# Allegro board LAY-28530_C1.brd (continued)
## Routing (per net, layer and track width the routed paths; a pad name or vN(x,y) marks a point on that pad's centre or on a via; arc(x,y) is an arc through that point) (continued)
DDR4_VTT: length 59.1
  TOP w0.254: C158.1 87.05,9.14 87.05,12.11 88.32,13.38 91.5,13.38 92,13.89 92,14.78 92.28,15.05 U38.19
  TOP w0.305: 172.27,27.86 172.65,28.24 C121.1
  TOP w0.508: R177.1 171.13,17.57 ; R182.1 171.13,13.13 ; R176.1 171.25,18.59 ; R175.1 171.25,19.61 ; R168.1 171.25,25.7 ; C119.1 170.24,27.86 ; R169.1 171.25,24.69 ; R171.1 171.13,22.65 ; R173.1 171.25,21.64 ; R174.1 171.13,20.62 ; R181.1 171.25,14.15 ; R170.1 171.13,23.67 ; C120.1 171.51,27.86
  BOTTOM w0.254: 110.94,12.62 C589.1 ; C589.1 112.19,12.62 ; C589.1 111.56,12 ; 113.48,12.62 C587.1 114.1,12 ; 110.92,12.11 C591.1 110.04,11.36 ; C585.1 117.14,12.62 ; C585.1 115.89,12.62 ; C585.1 116.52,12 ; 112.21,12.62 C588.1 ; C588.1 113.46,12.62 ; C588.1 112.83,12 ; 115.87,12.62 C586.1 115.25,12 ; 117.91,12 C584.1 ; C584.1 117.29,12.62 ; C584.1 118.54,12.62
  BOTTOM w0.381: 171,27.73 171.02,27.76 C486.1 ; C487.1 169.75,27.76 169.73,27.73 ; C593.1 v1(152.08,11.35)
  BOTTOM w0.508: R171.1 171.25,22.65 ; R176.1 171.38,18.59 ; R170.1 171.25,23.67 ; R169.1 171.25,24.69 ; C599.1 v1(156.9,10.84) ; C595.1 v1(138.99,11.35) ; R174.1 171.25,20.62 ; R168.1 171.25,25.7 ; R173.1 171.25,21.64 ; R181.1 171.38,14.15 ; C594.1 v1(143.57,11.22) ; R177.1 171.13,17.57 ; R175.1 171.38,19.61
  BOTTOM w0.533: C605.1 170.86,10.08 ; C605.1 170.24,9.46 ; C605.1 170.24,10.7 ; 170.36,12.51 R182.1 170.99,13.13 ; C600.1 170.86,11.48 ; C600.1 170.24,12.1 ; C600.1 170.24,10.86 ; 172.17,27.87 C485.1 172.79,28.5 ; 170.36,15.78 R180.1 170.99,15.16 ; 170.36,27.34 R166.1 170.99,26.72 ; 170.86,8.68 C606.1 170.24,9.31 ; 170.99,16.56 R178.1 170.36,15.94
  vias: v1(112.2,11.1) v1(113.21,11.1) v1(114.36,11.1) v1(115.88,11.1) v1(117.4,11.1) v1(118.55,11.1) v1(171.89,27.1) v1(171.89,25.96) v1(171.89,24.81) v1(171.89,23.67) v1(171.89,22.4) v1(171.89,21.38) v1(171.89,20.11) v1(171.89,18.97) v1(171.89,17.57) v1(171.89,16.18) v1(171.89,14.65) v1(171.89,13.13) v1(171.89,11.86) v1(171.89,10.84) v1(171.89,9.83)
EC1_AVDD10: length 22.1
  TOP w0.203: v1(107.37,135.68) 107.27,135.58 U5.47 ; U5.9 v1(102.43,137.59) ; U5.4 v1(104.44,137.59)
  TOP w0.508: R66.2 v1(110.55,127.05)
  L3_INT1 w0.508: v1(110.55,127.05) 110.55,128.19 107.37,131.37 v1(107.37,135.68) 106.48,136.57 105.47,136.57 104.45,137.59 v1(104.44,137.59) v1(102.43,137.59)
  BOTTOM w0.508: C205.2 102.42,137.57 v1(102.43,137.59) ; v1(104.44,137.59) 103.94,137.1 C204.2 ; C215.2 v1(107.37,135.68)
EC1_CLK_125M: length 80.3
  TOP w0.127: U21.W4 v2(135,70.81)
  TOP w0.203: R50.2 C42.1 110.29,130.1 110.67,130.48 v1(115.12,130.48)
  L3_INT1 w0.127: v1(115.12,130.48) 114.36,129.72 114.36,120.83 121.85,113.33 121.85,98.6 128.33,92.12 132.64,92.12 135.18,89.58 135.18,83.49 v1(134.68,82.98) 134.6,82.9 134.6,71.21 v2(135,70.81)
  BOTTOM w0.152: v1(134.68,82.98) 134.3,82.6 R404.1
EC1_DVDD10: length 17.4
  TOP w0.203: U5.22 99.37,132.38 v1(99.24,132.26)
  TOP w0.508: R74.2 v1(110.55,125.4)
  L3_INT1 w0.508: v1(110.55,125.4) 109.78,125.4 104.07,131.11 100.39,131.11 v1(99.24,132.26)
  BOTTOM w0.381: C222.2 99.62,132.64 v1(99.24,132.26)
EC1_DVDD_3V3: length 42.1
  TOP w0.203: U5.30 103.23,129.51 102.93,129.21 v1(102.93,128.32)
  TOP w0.381: R70.2 v1(114.99,126.16) ; R34.1 v1(95.69,136.07) ; R57.2 v1(114.99,129.46)
  L3_INT1 w0.381: v1(95.69,136.07) 98.23,136.07 98.99,135.3 98.99,134.16 98.61,133.78 98.61,131.49 101.78,128.32 v1(102.93,128.32)
  L4_INT2 w0.508: v1(114.99,126.16) 114.1,127.05 114.1,128.19 114.99,129.08 v1(114.99,129.46) 113.98,130.48 109.91,130.48 107.12,127.68 103.56,127.68 v1(102.93,128.32)
  BOTTOM w0.508: C236.2 102.93,129.84 v1(102.93,128.32) 102.29,127.68 C247.1 101.66,127.05 102.16,126.54 R221.2
EC1_DVDDRG: length 9.3
  TOP w0.203: v1(102.04,128.95) 102.84,129.75 U5.29
  BOTTOM w0.381: R217.2 97.21,128.57 97.59,128.95 98.23,128.95 99.5,130.22 C229.1
  BOTTOM w0.508: C229.1 100.77,130.22 101.02,129.97 C237.2 101.66,129.33 v1(102.04,128.95)
EC1_LED0/PHYAD0: length 181.9
  TOP w0.203: U5.35 105.24,130.2 106.99,128.45 110.55,128.45 112.45,126.54 R70.1 112.45,125.02 v1(112.58,124.89)
  TOP w0.305: C24.1 v1(92.89,138.81) 93.3,139.21 J4.17
  L3_INT1 w0.254: v1(92.89,138.81) 93.73,137.97 99.37,137.97 101.66,135.68 105.59,135.68 106.23,135.05 106.23,130.1 110.17,126.16 111.31,126.16 v1(112.58,124.89)
  L4_INT2 w0.203: v1(112.58,124.89) 112.58,107.11 109.53,104.06 109.53,65.96 112.32,63.17 112.32,47.55 109.91,45.13 109.91,39.67 105.72,35.48 105.72,15.92 109.66,11.99 109.66,10.21 114.23,5.64 v1(114.23,2.97)
  BOTTOM w0.203: C608.1 113.85,3.35 v1(114.23,2.97)
  BOTTOM w0.254: v1(114.23,2.97) 117.05,2.97 D12.4
EC1_LED1/CFG_LDO0: length 146.1
  TOP w0.203: R63.2 111.94,127.81 v1(111.44,128.32) 110.8,128.95 107.12,128.95 105.63,130.44 U5.36
  TOP w0.254: v1(112.71,136.32) 112.96,136.57 R31.1
  L3_INT1 w0.254: v1(111.44,128.32) 112.07,128.95 112.07,135.68 v1(112.71,136.32)
  L4_INT2 w0.203: v1(109.02,10.34) 109.02,11.99 104.7,16.3 104.7,35.23 109.53,40.05 109.53,45.39 111.94,47.8 111.94,62.79 109.15,65.58 109.15,104.4 112.07,107.32 112.07,124.64 111.44,125.27 v1(111.44,128.32)
  BOTTOM w0.203: R396.1 110.17,9.19 v1(109.02,10.34)
EC1_LED2/CFG_LDO1: length 7.6
  TOP w0.203: R57.1 v1(111.31,129.46) 107.37,129.46 106.37,130.46 106.37,131.58 U5.37
EC1_MDIN0: length 10.4
  TOP w0.104: v1(104.65,138.35) 104.88,138.12 104.88,137.44 104.83,137.39 U5.3
  L3_INT1 w0.104: J4.10 104.54,144.36 104.86,144.04 104.86,143.39 105.31,142.93 106.08,142.93 106.62,142.39 106.62,140.66 104.82,138.87 104.82,138.52 v1(104.65,138.35)
EC1_MDIN1: length 15.3
  TOP w0.104: v1(103.56,140.13) 103.56,140 103.68,139.88 103.68,137.44 103.64,137.39 U5.6
  L3_INT1 w0.104: v1(103.56,140.13) 103.73,139.96 103.73,139.57 104.05,139.25 104.73,139.25 105.21,139.73 105.21,140.51 102.93,142.8 102.93,144.81 104.21,146.1 104.21,146.75 104.36,146.9 J4.5
EC1_MDIN2: length 12.3
  TOP w0.104: U5.8 102.84,137.39 102.88,137.44 102.88,137.96 v1(102.5,138.35)
  L3_INT1 w0.104: J4.2 99.46,146.9 99.78,146.57 99.78,146.07 101.41,144.44 101.41,141.75 102.68,140.49 102.68,138.93 102.5,138.75 v1(102.5,138.35)
EC1_MDIN3: length 10.6
  TOP w0.104: v1(101.4,139.62) 101.68,139.34 101.68,137.44 101.63,137.39 U5.11
  L3_INT1 w0.104: v1(101.4,139.62) 101.6,139.43 101.6,139.21 101.49,139.1 101.3,139.1 100.39,140.02 100.39,142.14 99.14,143.38 99.14,143.96 99.54,144.36 J4.9
EC1_MDIP0: length 10.4
  TOP w0.104: v1(105.37,138.35) 105.19,138.17 105.19,137.44 105.24,137.39 U5.2
  L3_INT1 w0.104: J4.11 105.51,144.36 105.23,144.08 105.23,143.54 105.47,143.3 106.23,143.3 106.99,142.54 106.99,140.51 105.2,138.71 105.2,138.52 v1(105.37,138.35)
EC1_MDIP1: length 14.3
  TOP w0.104: v1(104.32,140.13) 104.2,140.13 103.99,139.92 103.99,137.44 104.03,137.39 U5.5
  L3_INT1 w0.104: v1(104.32,140.13) 104.1,139.9 104.1,139.73 104.2,139.62 104.58,139.62 104.84,139.89 104.84,140.36 102.56,142.64 102.56,144.97 103.84,146.25 103.84,146.71 103.65,146.9 J4.4
EC1_MDIP2: length 12.2
  TOP w0.104: U5.7 103.23,137.39 103.19,137.44 103.19,138.3 v1(103.24,138.35)
  L3_INT1 w0.104: J4.3 100.43,146.9 100.16,146.63 100.16,146.22 101.78,144.59 101.78,141.91 103.05,140.64 103.05,138.93 103.24,138.75 v1(103.24,138.35)
EC1_MDIP3: length 11.9
  TOP w0.104: U5.10 102.04,137.39 101.99,137.44 101.99,139.44 v1(102.16,139.62)
  L3_INT1 w0.104: J4.8 98.44,144.36 98.77,144.03 98.77,143.23 100.02,141.98 100.02,139.87 101.15,138.73 101.65,138.73 101.97,139.05 101.97,139.43 v1(102.16,139.62)
EC1_PHY_INT_N: length 80
  TOP w0.127: U21.Y3 v2(134.2,71.61)
  TOP w0.152: U5.34 104.83,129.97 106.86,127.94 110.42,127.94 111.56,126.79 v1(111.56,124.38)
  L3_INT1 w0.127: v1(111.56,124.38) 111.56,122.35 120.83,113.08 120.83,98.47 127.95,91.36 132.39,91.36 134.42,89.33 134.42,84.25 133.79,83.61 133.79,72.02 v2(134.2,71.61)
  BOTTOM w0.127: v2(134.2,71.61) 134.2,71.78 133.15,72.82 R281.2
EC1_RXC: length 97.6
  TOP w0.127: U21.T1 v2(137.4,73.21)
  TOP w0.152: R65.2 C45.1 100.89,125.65 100.64,125.4 100.64,122.6 101.53,121.71 114.61,121.71 115.5,122.6 v1(117.66,122.6)
  L3_INT1 w0.127: v1(117.66,122.6) 119.06,122.6 119.94,121.71 119.94,120.7 121.72,118.92 127.44,118.92 127.56,119.05 127.56,119.3 127.44,119.43 122.23,119.43 122.1,119.56 122.1,119.81 122.23,119.94 127.82,119.94 131.25,116.51 131.25,96.57 137.4,90.42 v2(137.4,73.21)
EC1_RXC/PHYAD1: length 6.1
  TOP w0.152: R73.2 99.75,127.3 100.26,127.81 R65.1 101.28,128.95 102.43,130.11 U5.28
EC1_RXCTL: length 95.8
  TOP w0.127: U21.W1 135.4,73.58
  TOP w0.152: v1(136.07,74.47) 135.4,73.79 135.4,73.58 ; R62.2 97.08,127.56 97.08,124.51 100.39,121.21 114.74,121.21 115.5,121.97 v1(116.13,121.97)
  L3_INT1 w0.127: v1(116.13,121.97) 121.6,116.51 128.71,116.51 129.85,115.36 129.85,96.95 129.6,96.7 128.71,96.7 128.58,96.57 128.58,96.44 128.71,96.31 129.98,96.31 130.1,96.19 130.1,96.06 129.98,95.93 128.71,95.93 128.58,95.81 128.58,95.68 128.71,95.55 130.1,95.55 130.23,95.43 130.23,95.3 130.1,95.17 128.58,95.17 128.45,95.04 128.45,94.92 128.58,94.79 131.5,94.79 136.33,89.96 136.33,74.72 v1(136.07,74.47)
EC1_RXCTL/PHYAD2: length 7.2
  TOP w0.152: R72.2 98.1,126.92 98.61,127.43 R62.1 98.74,128.19 100.64,128.19 100.89,128.45 100.89,129.08 102.04,130.22 U5.27
EC1_RXD0: length 97.1
  TOP w0.127: U21.V2 v2(135.8,72.41)
  TOP w0.152: v1(117.66,121.33) 115.63,121.33 115.12,120.83 100.13,120.83 96.7,124.25 96.7,128.19 R59.2
  L3_INT1 w0.127: v1(117.66,121.33) 122.1,116.89 127.44,116.89 127.56,117.02 127.56,117.27 127.44,117.4 124.64,117.4 124.52,117.52 124.52,117.78 124.64,117.9 128.45,117.9 130.23,116.13 130.23,96.57 136.71,90.09 136.71,74.09 136.2,73.58 136.2,72.81 v2(135.8,72.41)
EC1_RXD1: length 96.4
  TOP w0.127: U21.V1 v2(135.8,73.21)
  TOP w0.152: R55.2 96.2,124.25 100.01,120.44 116.01,120.44 v1(116.13,120.57)
  L3_INT1 w0.127: v1(116.13,120.57) 116.9,120.57 122.87,114.6 122.87,98.85 128.83,92.89 131.12,92.89 131.25,93.01 131.25,93.14 131.12,93.27 129.22,93.27 129.09,93.39 129.09,93.52 129.22,93.65 130.99,93.65 131.12,93.77 131.12,93.9 130.99,94.03 129.22,94.03 129.09,94.16 129.09,94.28 129.22,94.41 131.37,94.41 135.95,89.84 135.95,75.36 135.57,74.98 135.57,73.44 v2(135.8,73.21)
EC1_RXD1/CFG_MODE0: length 6.3
  TOP w0.152: U5.25 101.24,130.44 101.02,130.22 98.35,130.22 v1(97.97,129.84) 97.34,129.84 R55.1
  BOTTOM w0.152: v1(97.97,129.84) 97.59,129.46 R214.2
EC1_RXD2: length 97.6
  TOP w0.127: U21.U1 v2(136.6,73.21)
  TOP w0.152: v1(119.18,121.71) 119.18,121.59 117.66,120.06 99.88,120.06 95.43,124.51 95.43,130.22 R53.2
  L3_INT1 w0.127: v2(136.6,73.21) 137.09,73.7 137.09,90.22 130.61,96.7 130.61,116.51 128.71,118.41 122.87,118.41 122.74,118.29 122.74,118.03 122.87,117.9 123.75,117.9 123.88,117.78 123.88,117.52 123.75,117.4 122.36,117.4 119.18,120.57 v1(119.18,121.71)
EC1_RXD2/CFG_MODE1: length 4.9
  TOP w0.152: R53.1 v1(97.97,130.99) 99.24,130.99 99.84,131.58 U5.24
  BOTTOM w0.152: R210.2 v1(97.97,130.99)
EC1_RXD3: length 97.6
  TOP w0.127: U21.T2 v2(137.4,72.41)
  TOP w0.152: v1(120.71,121.71) 118.55,119.56 99.75,119.56 94.93,124.38 94.93,130.73 R49.2
  L3_INT1 w0.127: v2(137.4,72.41) 137.4,72.49 137.85,72.95 137.85,90.47 131.88,96.44 131.88,116.63 127.69,120.83 121.6,120.83 v1(120.71,121.71)
EC1_RXD3/CFG_MODE2: length 5.1
  TOP w0.152: R49.1 97.34,132.13 v1(97.97,132.13) 98.1,132.13 98.48,131.75 99.47,131.75 99.7,131.98 U5.23
  BOTTOM w0.152: R207.2 97.59,132.51 v1(97.97,132.13)
EC1_TXC: length 93.7
  TOP w0.152: v1(95.43,133.91) 96.56,132.78 U5.21
  L3_INT1 w0.127: v1(133.15,88.57) 131.78,89.94 131.6,89.94 131.46,89.8 131.46,89.62 131.86,89.23 131.86,89.05 131.72,88.91 131.54,88.91 130.49,89.96 127.56,89.96 118.55,98.98 118.55,111.94 115.25,115.24 113.09,115.24 111.44,116.89 111.44,118.41 111.31,118.54 111.18,118.54 111.05,118.41 111.05,117.78 110.93,117.65 110.8,117.65 110.67,117.78 110.67,119.81 110.04,120.44 102.55,120.44 100.01,122.98 98.86,122.98 95.43,126.41 v1(95.43,133.91)
  BOTTOM w0.152: v1(133.15,88.57) 139.12,82.6 139.12,80.19 138.74,79.8 R285.1
EC1_TXCTL: length 95.7
  TOP w0.152: U5.20 96.92,133.18 v1(96.2,133.91)
  L3_INT1 w0.127: v1(133.15,84.88) 133.66,85.39 133.66,88.69 131.88,90.47 127.56,90.47 119.82,98.22 119.82,111.3 115.37,115.75 114.1,115.75 113.98,115.87 113.98,118.03 113.85,118.16 113.59,118.16 113.47,118.03 113.47,116 113.34,115.87 113.09,115.87 112.96,116 112.96,118.41 112.83,118.54 112.58,118.54 112.45,118.41 112.45,117.14 112.32,117.02 112.07,117.02 111.94,117.14 111.94,119.17 110.29,120.83 102.67,120.83 100.13,123.37 99.12,123.37 96.2,126.29 v1(96.2,133.91)
  BOTTOM w0.152: v1(133.15,84.88) 133.66,84.88 135.18,83.36 135.18,81.07 134.55,80.44 R288.1
EC1_TXD0: length 89.7
  TOP w0.152: U5.19 97.29,133.58 v1(96.96,133.91)
  L3_INT1 w0.127: v1(133.15,83.61) 134.04,84.5 134.04,88.95 132.14,90.85 127.82,90.85 120.33,98.35 120.33,111.43 115.63,116.13 115.63,117.14 115.5,117.27 115.25,117.27 115.12,117.14 115.12,116.63 114.99,116.51 114.74,116.51 114.61,116.63 114.61,118.29 113.98,118.92 112.96,118.92 110.67,121.21 102.8,121.21 96.96,127.05 v1(96.96,133.91)
  BOTTOM w0.152: v1(133.15,83.61) 132.39,83.61 130.36,81.58 130.36,75.87 130.74,75.49 R296.1
EC1_TXD1: length 94.6
  TOP w0.152: U5.18 97.65,133.98 v1(96.7,134.92)
  L3_INT1 w0.127: v1(133.15,86.15) 130.1,89.2 127.31,89.2 117.79,98.73 117.79,111.68 115.5,113.97 115.37,113.97 115.25,113.84 115.25,112.7 115.12,112.57 114.99,112.57 114.86,112.7 114.86,114.09 114.74,114.22 114.61,114.22 114.48,114.09 114.48,113.08 114.36,112.95 114.23,112.95 114.1,113.08 114.1,114.22 113.98,114.35 113.85,114.35 113.72,114.22 113.72,113.84 113.59,113.71 113.34,113.71 107.37,119.68 102.04,119.68 99.5,122.22 98.48,122.22 94.42,126.29 94.42,134.16 95.18,134.92 v1(96.7,134.92)
  BOTTOM w0.152: R287.1 136.33,77.14 136.71,77.52 136.71,82.6 v1(133.15,86.15)
EC1_TXD2: length 90.3
  TOP w0.152: v1(97.47,134.92) 98.01,134.38 U5.17
  L3_INT1 w0.127: v1(97.47,134.92) 96.96,135.43 95.05,135.43 94.04,134.41 94.04,126.16 98.35,121.84 99.37,121.84 101.91,119.3 107.12,119.3 117.4,109.01 117.4,98.47 126.99,88.88 129.91,88.88 132.39,86.41 132.39,82.98 v1(133.15,82.22)
  BOTTOM w0.152: R295.1 130.87,76.15 130.87,81.07 132.01,82.22 v1(133.15,82.22)
EC1_TXD3: length 94.4
  TOP w0.152: v1(98.23,134.92) 98.37,134.78 U5.16
  L3_INT1 w0.127: v1(98.23,134.92) 97.72,134.41 95.18,134.41 94.8,134.03 94.8,126.41 98.61,122.6 99.62,122.6 102.16,120.06 109.66,120.06 109.78,119.94 109.78,119.81 109.66,119.68 108.64,119.68 108.51,119.56 108.51,119.43 108.64,119.3 109.91,119.3 110.04,119.17 110.04,119.05 109.91,118.92 109.15,118.92 109.02,118.79 109.02,118.67 109.15,118.54 110.04,118.54 110.17,118.41 110.17,118.29 110.04,118.16 109.91,118.16 109.78,118.03 109.78,117.78 112.83,114.73 115.25,114.73 118.17,111.81 118.17,98.85 127.37,89.65 130.23,89.65 132.45,87.42 v1(133.15,87.42)
  BOTTOM w0.152: v1(133.15,87.42) 137.47,83.11 R286.1
EC1_VDDREG: length 6.2
  TOP w0.203: v1(103.82,128.95) 103.64,129.13 U5.31
  BOTTOM w0.508: C235.2 103.94,129.08 v1(103.82,128.95) C251.1 R225.2
EMI1_MDC: length 106.3
  TOP w0.127: U21.W2 v2(135,72.41)
  TOP w0.152: R27.2 v1(96.58,138.86)
  TOP w0.508: R43.2 v1(116.64,134.67)
  L3_INT1 w0.127: v2(135,72.41) 134.93,72.47 134.93,82.22 135.57,82.85 135.57,89.71 132.77,92.5 128.58,92.5 122.36,98.73 122.36,113.59 115.63,120.32 115.63,130.73 117.28,132.38 117.28,134.03 v1(116.64,134.67)
  BOTTOM w0.104: 135,73.58 v2(135,72.41)
  BOTTOM w0.152: R277.1 135.57,75.49 135,74.92 135,73.58
  BOTTOM w0.254: v1(116.64,134.67) 116.13,135.18 116.13,136.45 112.96,139.62 103.18,139.62 102.67,140.13 97.85,140.13 v1(96.58,138.86)
EMI1_MDIO: length 108.8
  TOP w0.127: U21.Y1 v2(134.2,73.21)
  TOP w0.152: v1(95.43,138.73) 95.69,138.48 95.69,136.83 R37.2
  TOP w0.508: R46.2 v1(116.64,133.14)
  L3_INT1 w0.127: v2(134.2,73.21) 134.2,83.39 134.8,84 134.8,89.46 132.52,91.74 128.07,91.74 121.21,98.6 121.21,113.21 113.85,120.57 113.85,130.35 v1(116.64,133.14)
  BOTTOM w0.127: v2(134.2,73.21) 134.2,73.58
  BOTTOM w0.152: 134.2,73.58 134.2,74.82 133.53,75.49 133.53,76.5 132.26,77.77 R279.2
  BOTTOM w0.254: v1(95.43,138.73) 96.2,137.97 97.21,137.97 98.35,139.11 112.58,139.11 115.63,136.07 115.63,134.16 v1(116.64,133.14)
EMI2_MDC: length 76.8
  TOP w0.127: U21.P3 v2(138.99,71.61)
  TOP w0.152: v1(170.9,124.18) 171,124.28 171,126.16 167.58,129.58 U8.J18
  L3_INT1 w0.127: v1(170.9,124.18) 170.95,124.13 171,124.13 171.63,123.49 171.63,119.56 164.52,112.44 164.52,107.74 143.44,86.66 143.44,79.3 142.42,78.28 139.63,78.28 138.87,77.52 138.87,71.8 138.99,71.68 v2(138.99,71.61)
  BOTTOM w0.152: R227.1 170.95,124.13 v1(170.9,124.18)
EMI2_MDIO: length 75.2
  TOP w0.127: U21.P4 v2(138.99,70.81)
  TOP w0.152: v1(170.95,122.86) 170.95,122.91 169.6,124.25 169.6,125.41 U8.L18
  L3_INT1 w0.127: v2(138.99,70.81) 138.97,70.81 138.49,71.3 138.49,77.77 139.25,78.53 142.3,78.53 143.19,79.42 143.19,86.92 164.14,107.87 164.14,112.57 171,119.43 171,122.81 v1(170.95,122.86)
  BOTTOM w0.152: R229.1 v1(170.95,122.86)
EMMC_CLK: length 17.6
  TOP w0.152: U32.2 183.22,22.93 183.06,22.78 183.06,21.64 183.32,21.38 184.18,21.38 184.33,21.23 184.33,21.03 184.18,20.88 183.19,20.88 183.06,20.75 v1(183.06,13.76) ; v2(185.48,10.46) 185.48,10.74 U39.M6
  BOTTOM w0.152: v2(185.48,10.46) 183.83,12.11 183.83,13 v1(183.06,13.76)
EMMC_CMD: length 19.8
  TOP w0.152: U32.5 183.26,24.88 182.4,24.03 v1(182.4,21.13) ; U39.M5 185.24,11.71 v2(185.48,11.47)
  BOTTOM w0.152: v1(182.4,21.13) 182.61,20.93 182.61,19.05 182.76,18.9 183.04,18.9 183.19,19.05 183.19,19.58 183.34,19.73 183.55,19.73 183.7,19.58 183.7,18.36 183.85,18.21 184.05,18.21 184.21,18.36 184.21,18.56 184.36,18.72 184.56,18.72 184.71,18.56 184.71,17.57 185.1,17.19 185.1,11.86 v2(185.48,11.47)
EMMC_D0: length 19.7
  TOP w0.152: 178.11,25.53 179.04,25.53 180.9,23.67 v1(180.9,23.04) ; U39.A3 191.03,12.71 v2(191.32,13)
  BOTTOM w0.152: v2(191.32,13) 181.29,23.04 v1(180.9,23.04)
EMMC_D1: length 20.3
  TOP w0.152: v1(179.76,23.58) 178.11,23.58 ; v2(191.32,12.24) 191.29,12.21 U39.A4
  BOTTOM w0.152: v1(179.76,23.58) 181.75,23.58 191.95,13.38 191.95,12.88 v2(191.32,12.24)
EMMC_D2: length 19
  TOP w0.152: U39.A5 191.68,11.71 193.35,13.38 193.35,21 193.48,21.13 195.87,21.13 196.02,21.28 196.02,21.49 195.87,21.64 193.6,21.64 193.35,21.89 193.35,22.65 193.63,22.93 U33.2
EMMC_D3: length 19.4
  TOP w0.081: U39.B2 190.25,13.46 191.02,13.46
  TOP w0.152: U33.5 193.48,24.88 192.9,24.31 190.71,24.31 190.56,24.15 190.56,23.98 190.71,23.82 192.06,23.82 192.21,23.67 192.21,22.65 192.97,21.89 192.97,14.15 192.29,13.46 191.02,13.46
EMMC_RST: length 16.4
  TOP w0.152: v1(192.84,10.08) 194.29,11.53 Q13.3 200.67,11.53 R184.1 ; v2(186.49,11.22) U39.K5
  BOTTOM w0.152: v2(186.49,11.22) 186.49,11.1 187.89,9.7 192.46,9.7 v1(192.84,10.08)
EMMC_SEL_N: length 26.8
  TOP w0.152: R172.1 v1(201.94,23.04) 201,22.1 Q12.3 198.18,22.1 197.99,22.28 U33.1 ; v1(185.48,22.28) U32.1
  BOTTOM w0.152: v1(185.48,22.28) 185.49,22.27 201.18,22.27 v1(201.94,23.04)
EVDD: length 257.4
  TOP w0.254: U39.M4 185.5,12.21 v2(185.6,12.11) ; v2(191.57,11.22) 192.46,11.22 194.11,12.88 C142.2 ; v1(182.7,11.71) U39.P5 U39.N4 ; U39.P3 v1(182.68,12.71) ; U39.C6 189.27,11.21 v2(189.03,10.97)
  TOP w0.305: C81.1 v1(171.89,96.19) 171.89,95.51 C82.1 ; U21.K8 v2(143,67.61)
  TOP w0.381: C149.1 181.03,13 181.32,12.71 v1(182.68,12.71) ; v1(182.7,11.71) 180.76,11.71 179.76,10.72 C152.1
  TOP w0.508: v1(200.46,16.94) 200.72,16.69 R184.2 ; R157.1 175.44,35.74 v1(176.78,37.07) ; v1(171.89,96.19) 172.52,96.19 172.78,95.93 172.78,95.55 174.94,93.39 Q7.3 ; R158.1 177.48,36.37 v1(177.73,36.62) ; C113.1 187.38,31.22 v1(186.93,31.67) ; C142.2 196.14,18.34 v1(197.54,16.94) R179.2 ; R162.1 v1(196.91,35.99) ; R159.1 v1(183.06,36.62) ; R161.1 v1(195.13,35.99) ; R160.1 v1(184.71,36.62)
  TOP w0.762: v1(186.93,31.67) v1(186.93,36.62)
  L4_INT2 w0.254: v2(143,67.61) 143.49,68.11 143.49,68.7 143.31,68.88 141.03,68.88 140.39,69.52 140.39,74.22 140.65,74.47
  L4_INT2 w0.508: v1(197.54,16.94) 188.78,16.94 186.62,14.78 186.62,12.75 185.98,12.11 v2(185.6,12.11) 185.1,12.11 184.21,13 183.19,13 182.9,12.71 v1(182.68,12.71) 182.68,11.73 v1(182.7,11.71) ; v1(171.89,96.19) 171.89,96.44 171.38,96.95 164.9,96.95 151.69,83.74 151.69,79.3 151.19,78.79 v1(150.81,78.79) 143.57,78.79 142.68,77.9 142.68,76.5 140.65,74.47
  L4_INT2 w0.762: v1(197.54,16.94) v1(200.46,16.94) 199.95,17.45 199.95,34.34 198.3,35.99 v1(196.91,35.99) v1(195.13,35.99) 192.08,35.99 191.45,36.62 v1(186.93,36.62) v1(184.71,36.62) v1(183.06,36.62) v1(177.73,36.62) 177.22,36.62 v1(176.78,37.07) 174.05,39.8 174.05,53.39 169.35,58.09 169.35,90.35 171.89,92.89 v1(171.89,96.19)
  BOTTOM w0.254: v2(189.03,10.97) 189.29,11.22 v2(191.57,11.22)
  BOTTOM w0.508: C320.1 v1(150.81,78.79) ; Q21.1 177.09,99.24 176.21,100.12 172.52,100.12 171.89,99.49 C81.1 v1(171.89,96.19) ; v1(186.93,31.67) 186.93,30 J16.4
GPIO1_14_EMMC_SEL_N: length 107.5
  TOP w0.122: v2(148.6,60.41) 148.19,60.01 U21.C17
  TOP w0.152: SW3.3 v1(200.75,59.52) ; Q30.2 v1(201.43,24.99) ; Q29.2 201.28,29.18 v1(201.48,29.39) ; Q12.2 v1(201.43,19.91)
  L3_INT1 w0.122: v2(148.6,60.41) 150.55,60.41
  L3_INT1 w0.127: v1(201.43,24.99) 201.48,25.04 v1(201.48,29.39) 201.48,30.27 198.56,33.2 198.56,51.99 200.75,54.18 v1(200.75,59.51) 200.08,60.18 200.08,62.28 198.05,64.31 188.02,64.31 187.38,63.68 184.71,63.68 184.08,64.31 166.81,64.31 v1(166.05,63.55) 164.78,63.55 161.98,60.75 151.69,60.75 151.35,60.41 150.55,60.41
  L4_INT2 w0.127: v1(201.43,19.91) v1(201.43,24.99)
  BOTTOM w0.152: v1(166.05,63.55) 166.05,62.91 165.28,62.15 164.01,62.15 163.51,62.66 R290.1
GPIO3_0_WAKE_L: length 101.6
  TOP w0.152: P2.1 v1(48.35,62.28)
  L3_INT1 w0.127: v1(113.21,65.2) 112.96,64.95 93.66,64.95 93.27,64.56 90.99,64.56 90.48,64.06 87.94,64.06 86.83,65.16 63.65,65.16 60.76,62.28 v1(48.35,62.28)
  BOTTOM w0.152: R431.1 R432.1 128.2,76.5 128.07,76.63 128.07,77.77 126.93,78.92 115.37,78.92 112.32,75.87 112.32,70.66 113.72,69.26 113.72,65.71 v1(113.21,65.2)
GPIO3_1_CLKREQ_L: length 109.8
  TOP w0.127: v2(133.4,71.61) U21.AA3
  TOP w0.152: P2.7 v1(45.95,62.28)
  L3_INT1 w0.127: v1(45.95,62.28) 46.46,62.79 60.64,62.79 63.56,65.71 87.05,65.71 87.56,65.2 90.73,65.2 90.99,64.95 93.12,64.95 93.5,65.33 112.45,65.33 v1(113.21,66.09)
  L4_INT2 w0.122: v2(133.4,71.61) 133.4,73.34 133.15,73.58
  L4_INT2 w0.127: v1(128.71,77.39) 129.34,77.39 133.15,73.58
  BOTTOM w0.152: v1(128.71,77.39) R421.1 128.07,78.53 127.31,79.3 115.22,79.3 111.94,76.03 111.94,70.5 113.34,69.11 113.34,66.22 v1(113.21,66.09)
GPIO3_2_WAKE_L: length 116.5
  TOP w0.127: U21.AA1 133.8,73.19 133.41,73.58
  TOP w0.152: v1(122.99,75.23) 124.01,74.22 132.77,74.22 133.41,73.58 ; P3.1 v1(57.83,121.98)
  L3_INT1 w0.127: v1(122.99,75.23) 122.36,75.87 120.83,75.87 117.02,72.06 83.62,72.06 57.83,97.85 v1(57.83,121.98)
  BOTTOM w0.152: R420.1 v1(122.99,75.23)
GPIO3_3_CLKREQ_L: length 118.8
  TOP w0.127: U21.AB2 132.95,72.01 131.5,73.45 131.37,73.45
  TOP w0.152: 131.37,73.45 122.99,73.45 v1(121.21,75.23) ; P3.7 v1(57.84,124.38)
  L3_INT1 w0.127: v1(57.84,124.38) 57.33,123.87 57.33,97.64 83.3,71.68 117.66,71.68 v1(121.21,75.23)
  BOTTOM w0.152: v1(121.21,75.23) R422.1
I2C1_SCL: length 231.5
  TOP w0.127: 140.2,73.58 U21.N1
  TOP w0.152: U13.6 114.81,110.85 114.99,110.67 114.99,110.03 114.74,109.78 113.21,109.78 110.67,112.32 110.67,113.97 110.29,114.35 109.02,114.35 108.59,113.91 U10.6 108.59,112.26 v1(108.26,111.94) ; v1(116.77,80.19) 119.44,77.52 127.69,77.52 128.2,78.03 139.25,78.03 140.2,77.08 140.2,73.58 ; U38.54 91.28,30.37 J14.1
  L3_INT1 w0.127: v1(116.77,80.19) 111.69,85.27 111.69,108.51 v1(108.26,111.94) 103.18,111.94 88.07,127.05 88.07,133.78 84.51,137.34 59.49,137.34 58.22,138.61 55.68,138.61 53.65,136.57 v1(52.38,136.57)
  BOTTOM w0.152: R265.2 116.9,80.06 v1(116.77,80.19) 114.61,80.19 111.31,76.88 111.31,70.41 112.71,69.01 112.71,47.8 110.42,45.51 110.42,39.29 101.15,30.02 91.62,30.02 J14.1 ; R418.1 v1(52.38,136.57)
I2C1_SDA: length 228.3
  TOP w0.127: 140.62,73.58 140.62,72.43 U21.N2
  TOP w0.152: U38.53 91.78,28.65 J14.3 ; U13.5 115.46,109.99 114.86,109.4 113.09,109.4 110.29,112.19 110.29,113.81 110.14,113.97 109.4,113.97 109.24,113.8 U10.5 109.24,112.1 v1(109.4,111.94) ; v1(116.77,81.07) 119.94,77.9 127.56,77.9 128.07,78.41 139.38,78.41 140.62,77.17 140.62,73.58
  L3_INT1 w0.127: v1(116.77,81.07) 112.2,85.65 112.2,109.14 v1(109.4,111.94) 108.77,112.57 103.18,112.57 88.58,127.18 88.58,134.03 84.77,137.84 59.62,137.84 58.48,138.99 55.56,138.99 54.41,137.84 v1(52.38,137.84)
  BOTTOM w0.152: R260.2 116.9,81.2 v1(116.77,81.07) 114.86,81.07 110.86,77.07 110.86,70.22 112.26,68.82 112.26,47.99 109.97,45.7 109.97,39.48 100.96,30.47 96.26,30.47 J14.3 ; R417.1 v1(52.38,137.84)
I2C2_SCL: length 198
  TOP w0.127: 141,73.58 U21.M1
  TOP w0.152: v1(72.45,86.41) 72.3,86.55 U47.5 ; v1(155.76,93.27) 155.77,93.27 156.27,93.76 156.27,98.6 158.09,100.42 U48.14 ; 141,73.58 141,77.29 138.87,79.42 123.5,79.42 122.87,80.06 v1(122.36,80.06) ; U42.5 66.75,61.66 v1(66.6,61.52)
  L3_INT1 w0.127: v1(72.45,86.41) 73.97,84.88 108.26,84.88 114.1,79.04 120.45,79.04 121.47,80.06 v1(122.36,80.06)
  BOTTOM w0.152: v1(155.76,93.27) 155.76,93.26 151.07,88.57 136.2,88.57 135.06,89.71 123.88,89.71 122.87,88.69 122.87,84.63 123.25,84.25 123.25,80.95 v1(122.36,80.06) R264.2 ; v1(72.45,86.41) 72.07,86.03 72.07,66.98 v1(66.6,61.52) 66.35,61.26 35.74,61.26 R415.1
I2C2_SDA: length 200.5
  TOP w0.127: 141.41,73.58 141.41,72.42 U21.M2
  TOP w0.152: v1(155.76,94.03) 155.76,98.73 157.44,100.4 U48.15 ; U47.4 72.2,87.05 v1(72.45,87.3) ; v1(66.6,62.28) 66.72,62.16 U42.4 ; v1(122.36,81.2) 123.75,79.8 138.99,79.8 141.41,77.39 141.41,73.58
  L3_INT1 w0.127: v1(122.36,81.2) 121.98,81.2 120.2,79.42 114.26,79.42 108.42,85.27 74.48,85.27 v1(72.45,87.3)
  BOTTOM w0.152: v1(155.76,94.03) 150.68,88.95 136.36,88.95 135.22,90.09 123.72,90.09 122.48,88.85 122.48,84.47 122.87,84.09 122.87,81.71 v1(122.36,81.2) R259.2 ; R416.1 34.98,61.64 65.97,61.64 v1(66.6,62.28) 71.68,67.36 71.68,86.54 v1(72.45,87.3)
IFC_A0: length 22.9
  TOP w0.152: v1(184.33,62.53) 184.63,62.83 U25.23 ; U20.31 181.25,77.93 v1(182.05,77.14)
  BOTTOM w0.152: v1(182.05,77.14) 182.05,76.38 186.62,71.8 186.62,65.07 184.97,63.42 184.97,63.17 v1(184.33,62.53)
IFC_A1: length 22.9
  TOP w0.152: U20.26 195.42,77.93 186.87,69.39 186.87,62.53 186.67,62.33 U25.22
IFC_A2: length 23.4
  TOP w0.152: U25.20 186.69,61.33 187.38,62.02 187.38,69.26 195.55,77.43 U20.25
IFC_A3: length 23.4
  TOP w0.152: U20.24 195.69,76.93 187.89,69.14 187.89,61.9 186.82,60.83 U25.19
IFC_A4: length 23.6
  TOP w0.152: U25.17 186.58,59.83 188.4,61.64 188.4,69.01 195.82,76.43 U20.23
IFC_A5: length 23.6
  TOP w0.152: U20.22 195.96,75.93 188.91,68.88 188.91,61.52 186.72,59.33 U25.16
IFC_A6: length 24.1
  TOP w0.152: U25.14 186.86,58.33 189.41,60.88 189.41,68.76 196.09,75.43 U20.21
IFC_A7: length 24.1
  TOP w0.152: U25.13 187,57.83 189.92,60.75 189.92,68.63 196.23,74.94 U20.20
IFC_A8: length 19.7
  TOP w0.152: U25.12 187.26,57.33 190.43,60.5 190.43,64.06 196.31,69.93 U20.10
IFC_A9: length 19.7
  TOP w0.152: U25.11 187.39,56.83 190.94,60.37 190.94,63.93 196.44,69.43 U20.9
IFC_A10: length 20
  TOP w0.152: U20.8 196.58,68.94 191.45,63.8 191.45,60.25 187.03,55.83 U25.9
IFC_A11: length 20
  TOP w0.152: U25.8 187.29,55.33 191.95,59.99 191.95,63.68 196.71,68.44 U20.7
IFC_A12: length 20.3
  TOP w0.152: U20.6 196.85,67.93 192.4,63.48 192.4,59.67 187.05,54.33 U25.6
IFC_A13: length 20.4
  TOP w0.152: U25.5 187.32,53.83 192.84,59.36 192.84,63.29 196.98,67.43 U20.5
IFC_A14: length 20.7
  TOP w0.152: U20.4 197.12,66.93 193.29,63.1 193.29,59.04 187.08,52.83 U25.3
IFC_A15: length 20.7
  TOP w0.152: U25.2 187.34,52.33 193.73,58.72 193.73,62.91 197.25,66.43 U20.3
IFC_A16: length 75.6
  TOP w0.127: v2(148.6,68.41) 148.19,68.01 U21.C7
  TOP w0.152: SW2.5 v1(200.6,69.77) ; v1(188.27,72.69) 188.27,71.42 183.28,66.43 U20.54
  L3_INT1 w0.127: v2(148.6,68.41) 148.81,68.41 149.16,68.76 149.18,68.76 149.23,68.81 153.27,68.81 157.66,73.2 161.85,73.2 v1(162.11,73.45) 176.97,73.45 177.48,72.95 181.54,72.95 181.92,72.57 188.14,72.57 v1(188.27,72.69) 193.73,72.69 195,73.96 197.16,73.96 198.56,72.57 199.7,72.57 200.6,71.67 v1(200.6,69.77)
  BOTTOM w0.152: v1(162.11,73.45) 162.74,74.09 R299.1
IFC_A17: length 71.3
  TOP w0.152: SW2.6 203.63,68.5 204.15,69.01 204.15,75.23 203.76,75.61 201.48,75.61 200.3,74.43 U20.19 v1(196.82,74.43) ; U21.D7 147.39,68.01 v2(147.8,68.41)
  L3_INT1 w0.127: v2(147.8,68.41) 148.2,68.81 148.76,68.81 149.21,69.26 153.22,69.26 157.66,73.71 161.22,73.71 v1(161.35,73.84) 161.47,73.96 176.97,73.96 177.6,73.33 181.67,73.33 182.05,72.95 186.75,72.95 187.13,73.33 193.73,73.33 194.84,74.43 v1(196.82,74.43)
  BOTTOM w0.152: R292.1 162.87,75.11 161.6,73.84 v1(161.35,73.84)
IFC_A18: length 60.6
  TOP w0.127: U21.C8 148.19,67.21 v2(148.6,67.61)
  TOP w0.152: v1(195.64,73.2) 196.37,73.93 U20.18 200.11,73.93 201.73,72.32 SW2.3
  L3_INT1 w0.127: v2(148.6,67.61) 153.09,67.61 157.66,72.18 161.98,72.18 v1(162.11,72.31) 176.08,72.31 176.97,71.42 177.98,71.42 178.62,72.06 180.78,72.06 181.03,71.8 194.24,71.8 v1(195.64,73.2)
  BOTTOM w0.152: v1(162.11,72.31) 163.25,72.31 R304.1
IFC_A19: length 64.3
  TOP w0.127: U21.D8 v2(147.8,67.61)
  TOP w0.152: U20.11 v1(199.32,70.43) 199.93,71.05 SW2.4
  L3_INT1 w0.127: v1(199.32,70.43) 198.3,71.45 198.3,72.31 196.91,73.71 195.38,73.71 193.86,72.18 181.54,72.18 181.29,72.44 176.46,72.44 176.08,72.82 161.47,72.82 v1(161.35,72.69) 157.66,72.69 152.98,68.01 148.2,68.01 v2(147.8,67.61)
  BOTTOM w0.152: v1(161.35,72.69) 161.47,72.82 162.36,72.82 162.62,73.07 R302.1
IFC_A20: length 54
  TOP w0.127: v2(148.6,66.81) 148.19,66.41 U21.C9
  TOP w0.152: U20.12 196.67,70.93 v1(196.4,70.66)
  L3_INT1 w0.127: v1(196.4,70.66) 196.02,70.28 182.68,70.28 182.3,69.9 177.48,69.9 176.08,71.3 v1(162.62,71.3) 157.79,71.3 153.45,66.96 148.74,66.96 v2(148.6,66.81)
  BOTTOM w0.152: v1(162.62,71.3) 162.87,71.04 R308.1
IFC_A21: length 55.9
  TOP w0.127: v2(147.8,66.81) 147.39,66.41 U21.D9
  TOP w0.152: v1(195.64,72.06) 196.01,72.43 U20.15
  L3_INT1 w0.127: v2(147.8,66.81) 148.2,67.21 153.2,67.21 157.79,71.8 176.08,71.8 176.97,70.91 180.14,70.91 180.65,71.42 195,71.42 v1(195.64,72.06)
  BOTTOM w0.152: v1(195.64,72.06) 196.02,71.68 R315.2
IFC_A22: length 57.7
  TOP w0.127: v2(148.6,66.01) 148.19,65.61 U21.C10
  TOP w0.152: U20.2 198.78,65.93 199.57,66.72 v1(199.57,67.1)
  L3_INT1 w0.127: v2(148.6,66.01) 148.83,66.01 149.23,66.41 149.56,66.41 149.56,66.41 156.21,66.41 160.2,70.41 175.95,70.41 178.49,67.87 184.84,67.87 185.86,68.88 197.8,68.88 v1(199.57,67.1)
IFC_A23: length 66
  TOP w0.127: U21.D10 v2(147.8,66.01)
  TOP w0.152: U27.1 v1(194.37,54.85)
  L3_INT1 w0.127: v1(191.83,69.64) 183.7,69.64 182.94,68.88 177.98,68.88 176.08,70.79 157.79,70.79 153.71,66.7 149.05,66.7 148.76,66.41 148.2,66.41 v2(147.8,66.01)
  BOTTOM w0.152: v1(194.37,54.85) 193.35,55.86 193.35,64.95 190.43,67.87 190.43,68.88 191.19,69.64 v1(191.83,69.64)
IFC_A23_INVERT: length 89.7
  TOP w0.152: U27.2 194.49,53.9 v1(194.37,53.77) ; U48.6 160.04,96.02 160.37,95.68 169.47,95.68 171.38,93.77 171.38,66.22 v1(173.79,63.8) ; SW3.7 202.86,54.43 v1(203.38,53.9)
  L3_INT1 w0.127: v1(173.79,63.8) 173.67,63.93 172.78,63.93 172.4,63.55 172.4,59.36 174.68,57.07 176.97,57.07 179.25,54.79 180.4,54.79 182.81,52.37 192.97,52.37 v1(194.37,53.77)
  BOTTOM w0.152: v1(194.37,53.77) 195.76,52.37 201.86,52.37 v1(203.38,53.9) R140.2
IFC_A24: length 57.1
  TOP w0.127: v2(148.6,65.21) 148.19,64.81 U21.C11
  TOP w0.152: U24.1 v1(194.24,58.79)
  L3_INT1 w0.127: v1(191.83,67.23) 191.7,67.1 178.24,67.1 175.95,69.39 160.2,69.39 156.02,65.21 v2(148.6,65.21)
  BOTTOM w0.152: v1(191.83,67.23) 193.86,65.2 193.86,59.17 v1(194.24,58.79)
IFC_A24_INVERT: length 85.7
  TOP w0.152: U48.5 159.39,95.86 160.08,95.17 169.35,95.17 171,93.52 171,65.33 v1(172.9,63.42) ; SW3.6 v1(203.36,55.7) ; U24.2 v1(194.24,57.83)
  L3_INT1 w0.127: v1(172.9,63.42) 172.9,59.48 174.94,57.45 177.98,57.45 179.08,56.36 185.53,56.36 187,57.83 v1(194.24,57.83)
  BOTTOM w0.152: v1(194.24,57.83) 196.38,55.69 v1(203.36,55.69) 203.38,55.67 R138.2
IFC_A25: length 56
  TOP w0.127: U21.D11 v2(147.8,65.21)
  TOP w0.152: U23.1 v1(194.37,62.72)
  L3_INT1 w0.127: v2(147.8,65.21) 147.81,65.2 148.01,65.2 148.4,64.81 156.13,64.81 160.33,69.01 174.81,69.01 177.09,66.72 192.33,66.72 v1(192.91,67.29)
  BOTTOM w0.152: v1(192.91,67.29) 194.37,65.83 v1(194.37,62.72) 194.43,62.66 R467.1
IFC_A25_INVERT: length 87.9
  TOP w0.152: v1(173.67,63.04) 173.54,62.91 172.65,62.91 170.62,64.95 170.62,93.27 169.22,94.66 159.82,94.66 158.74,95.75 U48.4 ; v1(194.37,61.39) 194.75,61.77 U23.2 ; SW3.5 v1(203.38,56.97)
  L3_INT1 w0.127: v1(194.37,61.39) 191.32,58.34 178.49,58.34 177.98,57.83 175.19,57.83 173.67,59.36 v1(173.67,63.04)
  BOTTOM w0.152: v1(194.37,61.39) 198.79,56.96 v1(203.38,56.96) 203.87,57.45 R135.2
IFC_A26: length 15.4
  TOP w0.127: U21.C12 148.19,64.01 148.19,64.01 v2(148.6,64.41)
  L4_INT2 w0.122: v2(148.6,64.41) 150.2,64.41 150.55,64.06
  L4_INT2 w0.127: 150.55,64.06 153.6,61.01 153.6,59.1 153.85,58.85 156.27,58.85 157.66,57.45 v1(157.66,56.56)
  BOTTOM w0.152: R468.1 v1(157.66,56.56)
IFC_AD0: length 70.1
  TOP w0.122: U16.J8 189.46,85.03 186.37,85.03
  TOP w0.127: 149.61,69.21 149.4,69.21 149,68.81 U21.B6
  TOP w0.152: U25.26 178.12,62.79 v1(174.43,62.79) 174.17,62.53 171.89,62.53 168.33,66.09 159.95,66.09 157.79,68.25 152.58,68.25 151.62,69.21 149.61,69.21 ; 186.37,85.03 183.34,85.03 176.84,78.53 176.84,76.5 177.41,75.93 U20.35 v1(179.63,75.93)
  BOTTOM w0.152: v1(179.63,75.93) 176.78,75.93 175.32,74.47 175.32,65.58 174.43,64.69 v1(174.43,62.79)
IFC_AD1: length 65.7
  TOP w0.122: U16.K7 186.37,85.46
  TOP w0.127: 150.55,68.81 U21.A6
  TOP w0.152: 150.55,68.81 151.39,68.81 152.33,67.87 157.66,67.87 160.71,64.82 168.97,64.82 171.63,62.15 v1(174.94,62.15) 176.08,62.15 176.26,62.33 U25.27 ; 186.37,85.46 183.26,85.46 176.46,78.66 176.46,75.87 v1(177.03,75.3) 177.39,74.94 U20.37
  BOTTOM w0.152: v1(174.94,62.15) 174.94,64.44 175.82,65.33 175.82,74.09 v1(177.03,75.3)
IFC_AD2: length 70.7
  TOP w0.122: U16.J7 189.39,85.9 186.37,85.9
  TOP w0.127: 150.55,68.01 U21.A7
  TOP w0.152: v1(179.73,73.93) U20.39 176.61,73.93 176.08,74.47 176.08,78.79 183.19,85.9 186.37,85.9 ; U25.29 176.39,61.33 v1(176.21,61.52) 175.44,60.75 172.4,60.75 170.11,63.04 161.98,63.04 157.54,67.49 152.08,67.49 151.55,68.01 150.55,68.01
  BOTTOM w0.152: v1(176.21,61.52) 177.98,63.29 177.98,72.18 v1(179.73,73.93)
IFC_AD3: length 70.5
  TOP w0.122: U16.K6 186.37,86.26
  TOP w0.127: 150.55,67.61 149.4,67.61 149,67.21 U21.B8
  TOP w0.152: 176.73,72.93 v1(176.71,72.93) ; 176.73,72.93 175.7,73.96 175.7,78.92 183.05,86.26 186.37,86.26 ; 176.73,72.93 U20.41 ; 150.55,67.61 151.31,67.61 151.82,67.1 157.28,67.1 161.73,62.66 169.98,62.66 172.4,60.25 v1(175.57,60.25) 176.15,60.83 U25.30
  BOTTOM w0.152: v1(176.71,72.93) 176.46,72.68 176.46,65.07 175.32,63.93 175.32,62.66 175.57,62.41 v1(175.57,60.25)
IFC_AD4: length 72.6
  TOP w0.122: U16.K5 186.37,87.06
  TOP w0.127: U21.A8 150.55,67.21
  TOP w0.152: U25.32 177,59.83 176.59,60.25 v1(176.46,60.25) 176.33,60.25 175.82,59.74 172.27,59.74 169.73,62.28 161.47,62.28 157.03,66.72 151.69,66.72 151.21,67.21 150.55,67.21 ; v1(179.75,71.44) U20.44 176.83,71.44 175.32,72.95 175.32,79.04 183.34,87.06 186.37,87.06
  BOTTOM w0.152: v1(179.75,71.44) 178.36,70.05 178.36,62.15 v1(176.46,60.25)
IFC_AD5: length 77.4
  TOP w0.122: U16.K4 186.37,87.86
  TOP w0.127: U21.B9 149,66.41 149.41,66.83 150.55,66.83
  TOP w0.152: v1(180.5,70.43) U20.46 177.07,70.43 174.94,72.57 174.94,79.17 183.63,87.86 186.37,87.86 ; 150.55,66.83 150.96,66.83 151.44,66.34 156.77,66.34 161.22,61.9 169.47,61.9 172.14,59.23 v1(175.57,59.23) 175.67,59.33 U25.33
  BOTTOM w0.152: v1(175.57,59.23) 176.33,59.23 178.75,61.64 178.75,69.52 179.66,70.43 v1(180.5,70.43)
IFC_AD6: length 77.4
  TOP w0.122: U16.J4 189.39,88.3 186.37,88.3
  TOP w0.127: 150.55,66.41 U21.A9
  TOP w0.152: 186.37,88.3 183.55,88.3 174.55,79.3 174.55,72.31 177.43,69.43 U20.48 v1(179.76,69.43) ; 150.55,66.41 150.61,66.41 151.06,65.96 155.63,65.96 160.2,61.39 169.35,61.39 172.41,58.33 v1(176.21,58.33) U25.35
  BOTTOM w0.152: v1(179.76,69.43) 179.25,68.93 179.25,60.5 177.08,58.33 v1(176.21,58.33)
IFC_AD7: length 81.9
  TOP w0.122: 186.37,88.69 188.27,88.69 189.16,89.58 189.79,89.58 190.19,89.18 190.19,88.3 U16.H4
  TOP w0.127: 150.55,65.61 U21.A10
  TOP w0.152: 150.55,65.61 155.35,65.61 159.95,61.01 169.09,61.01 172.27,57.83 U25.36 v1(180.14,57.83) ; 186.37,88.69 183.44,88.69 174.17,79.42 174.17,71.3 177.03,68.44 U20.50 v1(180.52,68.44)
  BOTTOM w0.152: v1(180.52,68.44) 180.4,68.31 180.4,58.09 v1(180.14,57.83)
IFC_AD8: length 85
  TOP w0.127: 150.55,65.2 149.39,65.2 149,64.81 U21.B11
  TOP w0.152: U20.36 v1(180.78,75.43) 181.47,76.12 186.24,76.12 192.33,82.22 196.4,82.22 201.61,87.43 SW1.1 v1(204.01,87.43) ; v1(179.5,57.33) U25.37 172.14,57.33 168.84,60.63 159.7,60.63 155.12,65.2 150.55,65.2
  BOTTOM w0.152: v1(180.78,75.43) 181.29,74.93 181.29,68.12 180.78,67.61 180.78,57.71 180.4,57.33 v1(179.5,57.33) ; R245.2 204.02,87.42 v1(204.01,87.43)
IFC_AD9: length 84.4
  TOP w0.127: 150.55,64.81 U21.A11
  TOP w0.152: 150.55,64.81 154.88,64.81 159.44,60.25 168.59,60.25 172,56.83 U25.38 v1(180.13,56.83) ; v1(204.01,86.16) SW1.2 201.1,86.16 196.78,81.84 192.72,81.84 186.62,75.74 181.92,75.74 v1(181.54,75.36) 180.62,74.43 U20.38
  BOTTOM w0.152: v1(181.54,75.36) 181.67,75.23 181.67,67.87 181.16,67.36 181.16,57.58 180.41,56.83 v1(180.13,56.83) ; R251.2 204.02,86.15 v1(204.01,86.16)
IFC_AD10: length 84.7
  TOP w0.127: 150.51,64.39 149.38,64.39 149,64.01 U21.B12
  TOP w0.152: 150.51,64.39 154.66,64.39 159.19,59.87 168.33,59.87 172.37,55.83 U25.40 v1(179.48,55.83) ; v1(204.01,84.89) SW1.3 200.47,84.89 197.03,81.45 193.09,81.45 185.6,73.96 183.08,73.96 v1(182.56,73.43) U20.40
  BOTTOM w0.152: v1(182.56,73.43) 182.17,73.05 182.17,67.74 181.54,67.1 181.54,57.2 180.17,55.83 v1(179.48,55.83) ; R253.2 204.02,84.88 v1(204.01,84.89)
IFC_AD11: length 84.7
  TOP w0.127: 150.55,64.01 U21.A12
  TOP w0.152: v1(180.11,55.33) U25.41 172.23,55.33 168.2,59.36 159.19,59.36 154.54,64.01 150.55,64.01 ; U20.42 182.42,72.43 v1(183.44,73.45) 185.73,73.45 193.22,80.95 197.16,80.95 199.83,83.62 SW1.4 v1(204.01,83.62)
  BOTTOM w0.152: v1(183.44,73.45) 182.68,72.69 182.68,67.61 181.92,66.85 181.92,56.94 180.31,55.33 v1(180.11,55.33) ; v1(204.01,83.62) 204.02,83.61 R255.2
IFC_AD12: length 83
  TOP w0.127: 150.55,63.21 149.8,63.21 149.8,63.21 U21.A13
  TOP w0.152: v1(204.01,82.34) SW1.5 199.19,82.34 197.41,80.57 193.48,80.57 184.71,71.8 184.19,71.8 v1(183.32,70.93) U20.45 ; v1(179.45,54.33) U25.43 169.8,54.33 165.66,58.47 158.81,58.47 154.07,63.21 150.55,63.21
  BOTTOM w0.152: v1(183.32,70.93) 183.19,70.81 183.19,67.49 182.3,66.6 182.3,56.69 179.94,54.33 v1(179.45,54.33) ; R257.2 204.02,82.34 v1(204.01,82.34)
IFC_AD13: length 85.1
  TOP w0.127: U21.B14 149,62.41 149.41,62.83 150.55,62.83
  TOP w0.152: v1(180.21,53.83) U25.44 169.67,53.83 166.05,57.45 159.19,57.45 153.81,62.83 150.55,62.83 ; U20.47 183.23,69.93 v1(184.21,70.91) 184.46,70.91 193.73,80.19 197.67,80.19 198.55,81.07 SW1.6 v1(204.02,81.07)
  BOTTOM w0.152: v1(184.21,70.91) 183.57,70.28 183.57,67.23 182.68,66.34 182.68,56.06 180.46,53.83 v1(180.21,53.83) ; v1(204.02,81.07) 204.02,81.07 R262.2
IFC_AD14: length 83.8
  TOP w0.127: 150.55,62.41 149.8,62.41 U21.A14
  TOP w0.152: v1(179.46,52.83) U25.46 174.61,52.83 174.43,53.01 168.08,53.01 164.01,57.07 158.93,57.07 153.59,62.41 150.55,62.41 ; v1(204.01,79.8) SW1.7 193.98,79.8 184.08,69.9 v1(184.08,69.01) 184.01,68.94 U20.49
  BOTTOM w0.152: v1(204.01,79.8) 204.02,79.8 R268.2 ; v1(179.46,52.83) 180.47,52.83 183.06,55.42 183.06,66.09 184.08,67.1 v1(184.08,69.01)
IFC_AD15: length 86.6
  TOP w0.127: 150.55,62.02 149.41,62.02 149,61.61 U21.B15
  TOP w0.152: 150.55,62.02 153.35,62.02 159.7,55.67 164.65,55.67 167.82,52.5 174.17,52.5 174.34,52.33 U25.47 v1(180.23,52.33) ; v1(204.01,78.53) SW1.8 202.12,78.53 201.22,79.42 194.24,79.42 184.97,70.15 v1(184.97,69.01) 183.89,67.93 U20.51
  BOTTOM w0.152: v1(184.97,69.01) 184.97,67.36 183.44,65.83 183.44,55.17 180.61,52.33 v1(180.23,52.33) ; R276.2 204.02,78.53 v1(204.01,78.53)
IFC_AVD: length 110.2
  TOP w0.127: v2(148.6,62.01) 148.19,61.61 U21.C15 ; U16.C4 v2(194.23,87.46)
  TOP w0.152: SW2.8 201.48,65.96 v1(201.22,66.22) ; U25.25 182.21,63.33 v1(185.1,66.22) ; U25.48 v1(179.56,51.83)
  L3_INT1 w0.127: v2(194.23,87.46) 193.73,86.97 193.73,86.54 200.84,79.42 200.84,72.57 201.48,71.93 201.48,66.47 v1(201.22,66.22) v1(185.1,66.22) 163.12,66.22 v1(162.49,65.58) 160.58,65.58 157.96,62.95 149.7,62.95 148.76,62.01 v2(148.6,62.01)
  BOTTOM w0.152: v1(179.56,51.83) 180.75,51.83 183.83,54.91 183.83,64.95 v1(185.1,66.22) ; v1(162.49,65.58) 163.12,64.95 R321.2
IFC_CLE: length 82.7
  TOP w0.127: U16.D5 v2(194.23,86.66) ; U21.C16 148.19,60.81 v2(148.6,61.21)
  TOP w0.152: v1(201.74,74.86) SW2.1
  L3_INT1 w0.127: v2(148.6,61.21) 148.72,61.21 149.92,62.41 159.57,62.41 160.84,63.68 163,63.68 164.78,65.45 184.46,65.45 185.1,64.82 186.37,64.82 187,65.45 198.81,65.45 199.32,64.95 200.72,64.95 201.86,66.09 201.86,72.18 201.22,72.82 201.22,74.34 v1(201.74,74.86) 201.74,79.15 v2(194.23,86.66)
IFC_CS0: length 57.6
  TOP w0.127: v2(146.2,62.81) 145.8,63.21 U21.F13
  L3_INT1 w0.127: v1(172.4,67.36) 172.14,67.1 v1(162.49,67.1) 160.58,67.1 156.94,63.46 147.41,63.46 147.16,63.21 146.6,63.21 v2(146.2,62.81)
  BOTTOM w0.152: v1(172.4,67.36) 172.4,76.63 178.87,83.11 178.87,86.54 180.14,87.81 180.78,87.81 181.85,88.88 U15.4 ; v1(162.49,67.1) 163.38,67.1 R317.1
IFC_CS1: length 60.8
  TOP w0.127: v2(147,62.81) 146.6,62.41 U21.E14
  L3_INT1 w0.127: v2(147,62.81) 147.15,62.81 147.54,63.21 157.2,63.21 160.58,66.6 v1(161.85,66.6) 173.54,66.6 v1(173.92,66.98)
  BOTTOM w0.152: v1(173.92,66.98) 172.78,68.12 172.78,76.38 179.25,82.85 179.25,86.28 180.27,87.3 181.41,87.3 183.8,89.68 U15.7 ; R319.1 162.87,66.6 v1(161.85,66.6)
IFC_OE_N: length 98.5
  TOP w0.127: U16.D4 v2(194.23,88.26)
  TOP w0.152: v1(180.65,77.14) 179.95,76.43 U20.34 ; v1(199.57,65.58) 199.57,63.17 200.69,62.06 SW3.1 ; U21.D15 v2(147.8,61.21)
  L3_INT1 w0.127: v2(147.8,61.21) 148.2,61.61 148.76,61.61 149.81,62.66 158.17,62.66 159.82,64.31 v1(162.49,64.31) 164.01,65.83 184.59,65.83 185.1,65.33 v1(185.86,65.33) 186.37,65.83 199.32,65.83 v1(199.57,65.58)
  BOTTOM w0.127: 186.24,82.22 190.81,82.22 193.48,84.88 193.48,87.51 v2(194.23,88.26)
  BOTTOM w0.152: 186.24,82.22 184.71,82.22 180.65,78.15 v1(180.65,77.14) 185.86,71.93 v1(185.86,65.33) ; R324.2 163.12,64.31 v1(162.49,64.31)
IFC_RB0: length 55.9
  TOP w0.127: U21.F12 145.8,64.01 v2(146.2,64.41)
  L3_INT1 w0.127: v1(174.55,68.25) 174.3,67.99 162.24,67.99 v1(161.85,67.61) 160.46,67.61 156.56,63.72 147.72,63.72 147.42,64.01 146.59,64.01 v2(146.2,64.41)
  BOTTOM w0.152: v1(161.85,67.61) 163.12,67.61 R314.1 ; v1(174.55,68.25) 174.55,76.76 181.85,84.05 U15.13 181.85,85.83 182.05,86.03 182.94,86.03 183.15,85.81 U15.11
IFC_RB1: length 55.2
  TOP w0.127: U21.E11 v2(147,65.21)
  L3_INT1 w0.127: v1(173.54,68.5) v1(162.87,68.5) 160.84,68.5 156.35,64.01 148.43,64.01 148.19,64.25 148.19,64.63 148.01,64.81 147.39,64.81 v2(147,65.21)
  BOTTOM w0.152: v1(162.87,68.5) 163,68.5 R312.1 ; v1(173.54,68.5) 173.54,76.38 181.2,84.04 U15.14 181.2,85.94 181.67,86.41 183.32,86.41 183.8,85.93 U15.10
IFC_TE: length 64.3
  TOP w0.127: 150.55,61.61 149.8,61.61 U21.A15
  TOP w0.152: SW2.2 201.74,73.59 v1(201.73,73.58) ; 150.55,61.61 151.22,61.61 151.31,61.52 v2(151.44,61.52)
  L3_INT1 w0.127: v2(151.44,61.52) 159.19,61.52 160.97,63.29 163.12,63.29 164.9,65.07 184.33,65.07 184.97,64.44 186.62,64.44 187.25,65.07 198.56,65.07 199.07,64.56 200.97,64.56 202.24,65.83 202.24,73.07 v1(201.73,73.58)
IFC_WE_N: length 91
  TOP w0.127: U21.F11 v2(146.2,65.21) ; U16.C7 v2(194.27,85.11)
  TOP w0.152: U20.13 196.03,71.44 192.97,68.37 v1(191.06,68.37)
  L3_INT1 w0.122: v2(194.27,85.11) 197.16,82.22
  L3_INT1 w0.127: v2(146.2,65.21) 146.59,65.61 155.91,65.61 160.2,69.9 v1(162.74,69.9) 162.87,70.03 175.82,70.03 178.36,67.49 190.18,67.49 v1(191.06,68.37) 192.72,68.37 194.49,66.6 200.34,66.6 201.1,67.36 201.1,71.68 200.34,72.44 200.34,79.04 197.16,82.22
  BOTTOM w0.152: R402.1 v1(191.06,68.37) ; v1(162.74,69.9) 162.87,70.03 R310.2
IFC_WP_N: length 60.2
  TOP w0.122: U21.D16 v2(147,61.21)
  TOP w0.152: SW3.2 v1(200.75,60.79)
  L3_INT1 w0.122: v2(147,61.21) 147.4,60.81 148.76,60.81 150.55,60.81
  L3_INT1 w0.127: 150.55,60.81 151.36,60.81 151.69,61.14 161.73,61.14 165.28,64.69 184.21,64.69 184.84,64.06 187.13,64.06 187.76,64.69 198.3,64.69 200.75,62.25 v1(200.75,60.78)
INTVCC: length 27.9
  TOP w0.305: U9.21 205.42,110.29 D8.A v1(206.3,110.28) C71.1 208.34,110.28 208.72,109.9 208.72,107.74 209.35,107.11 210.88,107.11 211.38,107.62 R93.2 211.38,109.52 R92.1 ; v1(209.23,114.09) 209.09,114.23 U9.3 ; 211.38,118.67 v1(212.4,118.67)
  BOTTOM w0.305: v1(212.4,118.67) 209.99,116.25 209.99,114.86 v1(209.23,114.09) 209.23,111.94 207.57,110.28 v1(206.3,110.28)
JTAG_TCK: length 51.4
  TOP w0.127: U21.E18 146.6,59.21 v2(147,58.81)
  L3_INT1 w0.127: v2(147,58.81) 147.39,58.41 148.76,58.41 149,58.18 150.55,56.62 156.33,50.85 162.49,50.85 166.05,47.29 182.43,47.29 v1(184.21,45.51)
  BOTTOM w0.152: U44.10 186.67,46.96 185.86,46.15 184.84,46.15 v1(184.21,45.51)
JTAG_TDI: length 49
  TOP w0.127: U21.C18 v2(148.6,58.81)
  L3_INT1 w0.127: v2(148.6,58.81) 148.81,58.81 155.76,51.86 162.24,51.86 166.43,47.67 183.32,47.67 v1(184.21,46.78)
  BOTTOM w0.152: U44.12 185.19,47.76 v1(184.21,46.78)
JTAG_TDO: length 50
  TOP w0.152: U21.D17 v2(147.8,59.61)
  L3_INT1 w0.127: v2(147.8,59.61) 151.06,59.61 156.14,54.53 160.97,54.53 167.06,48.44 183.83,48.44 v1(185.48,46.78)
  BOTTOM w0.152: v1(185.48,46.78) 186.06,47.37 U44.11
JTAG_TMS: length 51.9
  TOP w0.127: U21.E17 146.6,60.01 v2(147,59.61)
  L3_INT1 w0.127: v1(185.48,45.51) 184.97,46.02 184.97,46.66 183.57,48.05 166.81,48.05 161.85,53.01 156.88,53.01 150.68,59.21 147.4,59.21 147,59.61 v2(147,59.61)
  BOTTOM w0.152: v1(185.48,45.51) 185.86,45.51 186.91,46.57 U44.9
LANEA_RX_N: length 122.3
  TOP w0.104: P3.23 v1(54.67,133.98)
  L3_INT1 w0.104: v1(54.67,133.98) 54.45,134.19 54.08,134.19 53.9,134.02 53.9,124.76 54.92,123.75 54.92,96.08 80.97,70.03 113.98,70.03 117.03,66.97 121.1,66.97 121.67,66.4 122.8,66.4 v1(122.99,66.6)
  BOTTOM w0.104: C365.2 123.75,66.47 123.65,66.37 123.22,66.37 v1(122.99,66.6)
LANEA_RX_P: length 123.5
  TOP w0.104: P3.25 v1(54.67,134.78)
  L3_INT1 w0.104: v1(54.67,134.78) 54.45,134.57 53.93,134.57 53.53,134.17 53.53,124.61 54.55,123.59 54.55,95.92 80.82,69.65 113.82,69.65 116.88,66.6 120.94,66.6 121.4,66.14 121.4,66.14 121.51,66.03 122.8,66.03 v1(122.99,65.83)
  BOTTOM w0.104: C377.2 123.75,65.96 123.65,66.07 123.22,66.07 v1(122.99,65.83)
LANEA_TX_N: length 123
  TOP w0.104: v1(57.59,137.18) P3.31
  L3_INT1 w0.104: v1(122.99,68.63) 122.8,68.43 117.36,68.43 114.75,71.04 82.24,71.04 56.19,97.09 56.19,137.08 56.51,137.4 57.37,137.4 v1(57.59,137.18)
  BOTTOM w0.104: C344.1 123.75,68.5 123.65,68.4 123.22,68.4 v1(122.99,68.63)
LANEA_TX_P: length 124.2
  TOP w0.104: v1(57.59,137.98) P3.33
  L3_INT1 w0.104: v1(122.99,67.87) 122.8,68.06 117.21,68.06 114.6,70.67 82.09,70.67 55.82,96.94 55.82,137.23 56.35,137.77 57.37,137.77 v1(57.59,137.98)
  BOTTOM w0.104: C355.1 123.75,67.99 123.65,68.1 123.22,68.1 v1(122.99,67.87)
LANEB_RX_N: length 73.6
  TOP w0.104: U8.V6 155.63,120.38 155.63,119.3 155.08,118.75 155.08,102.28 142.68,89.89 132.77,89.89 130.42,87.53 130.42,86.39 130.32,86.28 v1(130.02,86.28)
  L3_INT1 w0.104: v1(128.33,66.34) 128.36,66.34 128.56,66.15 128.88,66.15 129.35,66.62 129.35,84.15 130.36,85.15 130.36,85.94 v1(130.02,86.28)
  BOTTOM w0.104: C366.2 129.09,66.22 128.98,66.11 128.56,66.11 v1(128.33,66.34)
LANEB_RX_P: length 75.4
  TOP w0.104: U8.U6 155.43,121.28 155.93,120.78 155.93,119.18 155.38,118.62 155.38,102.16 142.8,89.58 132.9,89.58 130.72,87.41 130.72,86.39 130.83,86.28 v1(131.12,86.28)
  L3_INT1 w0.104: v1(131.12,86.28) 130.73,85.89 130.73,85 129.72,84 129.72,66.47 129.03,65.78 128.52,65.78 v1(128.33,65.58)
  BOTTOM w0.104: v1(128.33,65.58) 128.56,65.81 128.98,65.81 129.09,65.7 C381.2
LANEB_TX_N: length 69.8
  TOP w0.104: C56.1 153.51,114.82 153.51,102.24 142.43,91.16 132.65,91.16 129.17,87.68 129.17,85.82 130.65,84.34 130.65,83.97 130.54,83.87 v1(130.25,83.87)
  TOP w0.127: U21.Y11 v2(134.2,65.21)
  L3_INT1 w0.104: v1(130.25,83.87) 130.61,83.5 130.61,81.47 130.88,81.2 130.88,68.44 131.36,67.96 131.58,67.96 131.59,67.96 131.92,67.96 133.24,66.63 133.42,66.63 134.48,65.58 134.48,65.49 v2(134.2,65.21)
LANEB_TX_P: length 69.7
  TOP w0.104: v1(131.35,83.87) 131.06,83.87 130.95,83.97 130.95,84.47 129.47,85.95 129.47,87.55 132.77,90.85 142.55,90.85 153.81,102.12 153.81,114.82 C57.1
  TOP w0.127: U21.W11 v2(135,65.21)
  L3_INT1 w0.104: v1(131.35,83.87) 130.98,83.5 130.98,81.62 131.25,81.35 131.25,68.6 131.53,68.31 131.53,68.24 131.59,68.19 132.02,68.19 133.34,66.86 133.52,66.86 134.71,65.67 134.71,65.49 v2(135,65.21)
LANEC_RX_N: length 95.5
  TOP w0.104: P2.23 v1(36.35,62.28)
  L3_INT1 w0.104: v1(124.39,61.64) 124.19,61.84 118.21,61.84 113.45,66.6 62.43,66.6 59.9,64.07 36.9,64.07 36.14,63.3 36.14,62.49 v1(36.35,62.28)
  BOTTOM w0.104: v1(124.39,61.64) 124.62,61.87 125.05,61.87 125.15,61.77 C427.2
LANEC_RX_P: length 96.1
  TOP w0.104: P2.25 v1(35.55,62.28)
  L3_INT1 w0.104: v1(124.39,62.41) 124.19,62.21 118.36,62.21 113.61,66.97 62.28,66.97 59.75,64.44 36.74,64.44 35.76,63.46 35.76,62.49 v1(35.55,62.28)
  BOTTOM w0.104: C409.2 125.15,62.28 125.05,62.18 124.62,62.18 v1(124.39,62.41)
LANEC_TX_N: length 103.1
  TOP w0.104: P2.31 v1(33.15,62.28)
  L3_INT1 w0.104: v1(128.2,63.55) 127.95,63.8 117.77,63.8 113.7,67.88 60.54,67.88 58.12,65.46 34.74,65.46 32.94,63.67 32.94,62.49 v1(33.15,62.28)
  BOTTOM w0.104: C403.1 129.09,63.67 128.98,63.78 128.43,63.78 v1(128.2,63.55)
LANEC_TX_P: length 103.7
  TOP w0.104: P2.33 v1(32.35,62.28)
  L3_INT1 w0.104: v1(32.35,62.28) 32.57,62.5 32.57,63.82 34.58,65.83 57.97,65.83 60.38,68.25 113.85,68.25 117.92,64.17 128.06,64.17 v1(128.2,64.31)
  BOTTOM w0.104: C391.1 129.09,64.19 128.98,64.08 128.43,64.08 v1(128.2,64.31)
